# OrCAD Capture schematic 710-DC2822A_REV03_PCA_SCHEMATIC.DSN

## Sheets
1 PAGE1: company: ANALOG DEVICES; note: DEMO BOARD BILL OF MATERIALS; note: HIGH EFFICIENCY 65V/100mA SYNCHRONOUS BUCK
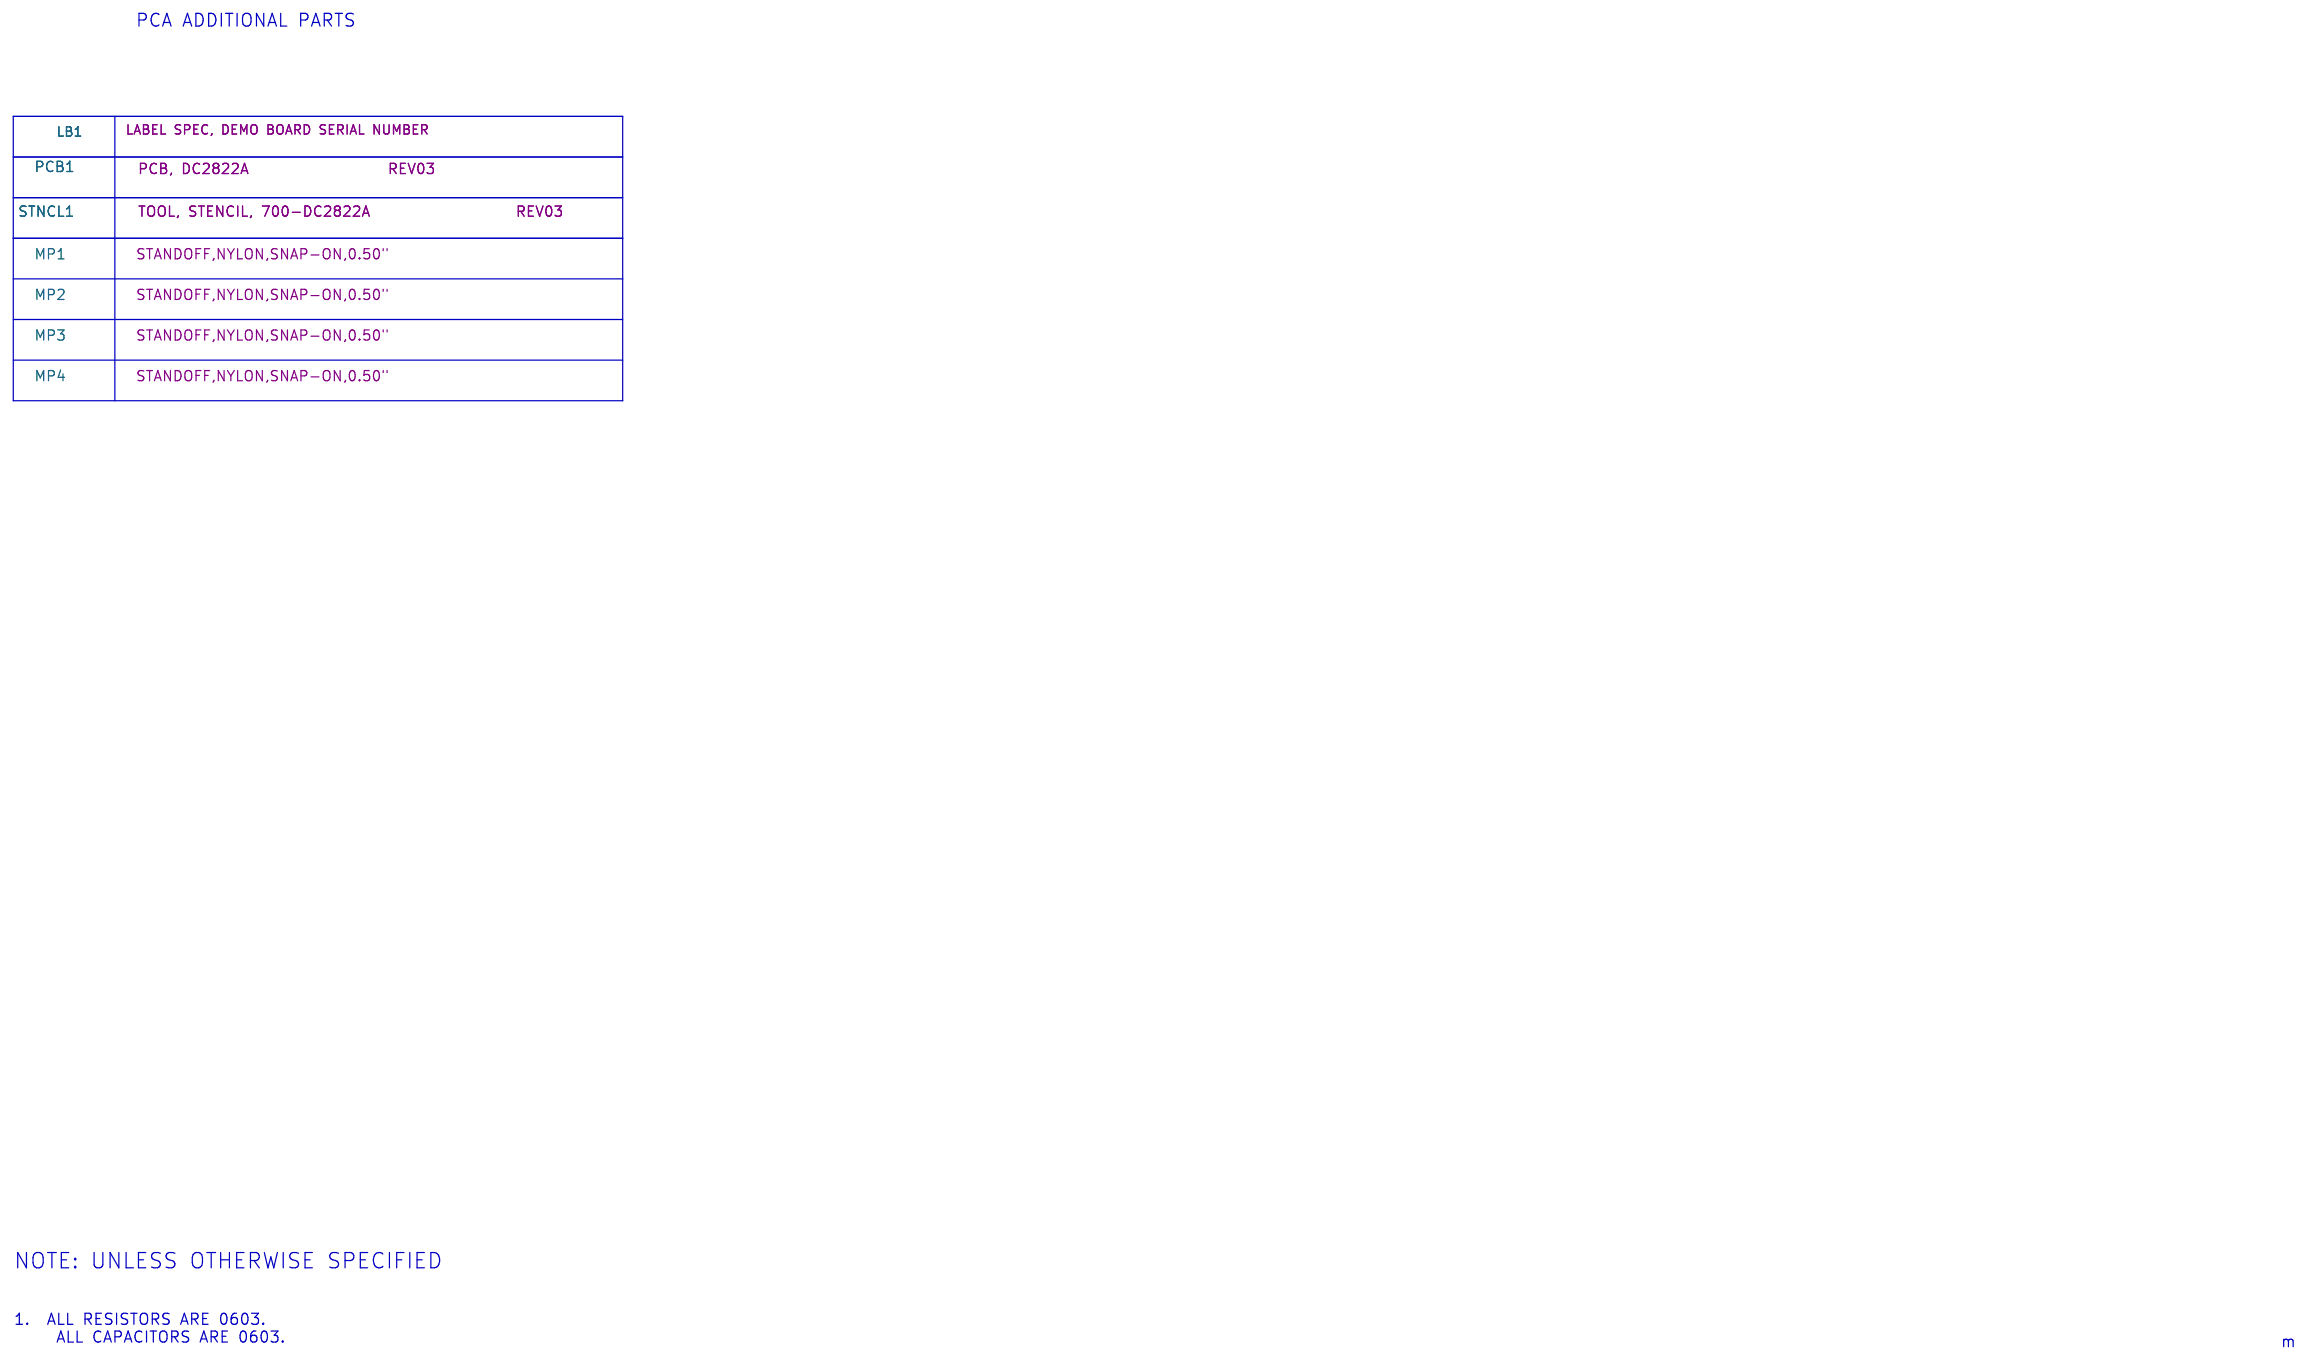
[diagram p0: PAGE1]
2 DC2822A: size Custom
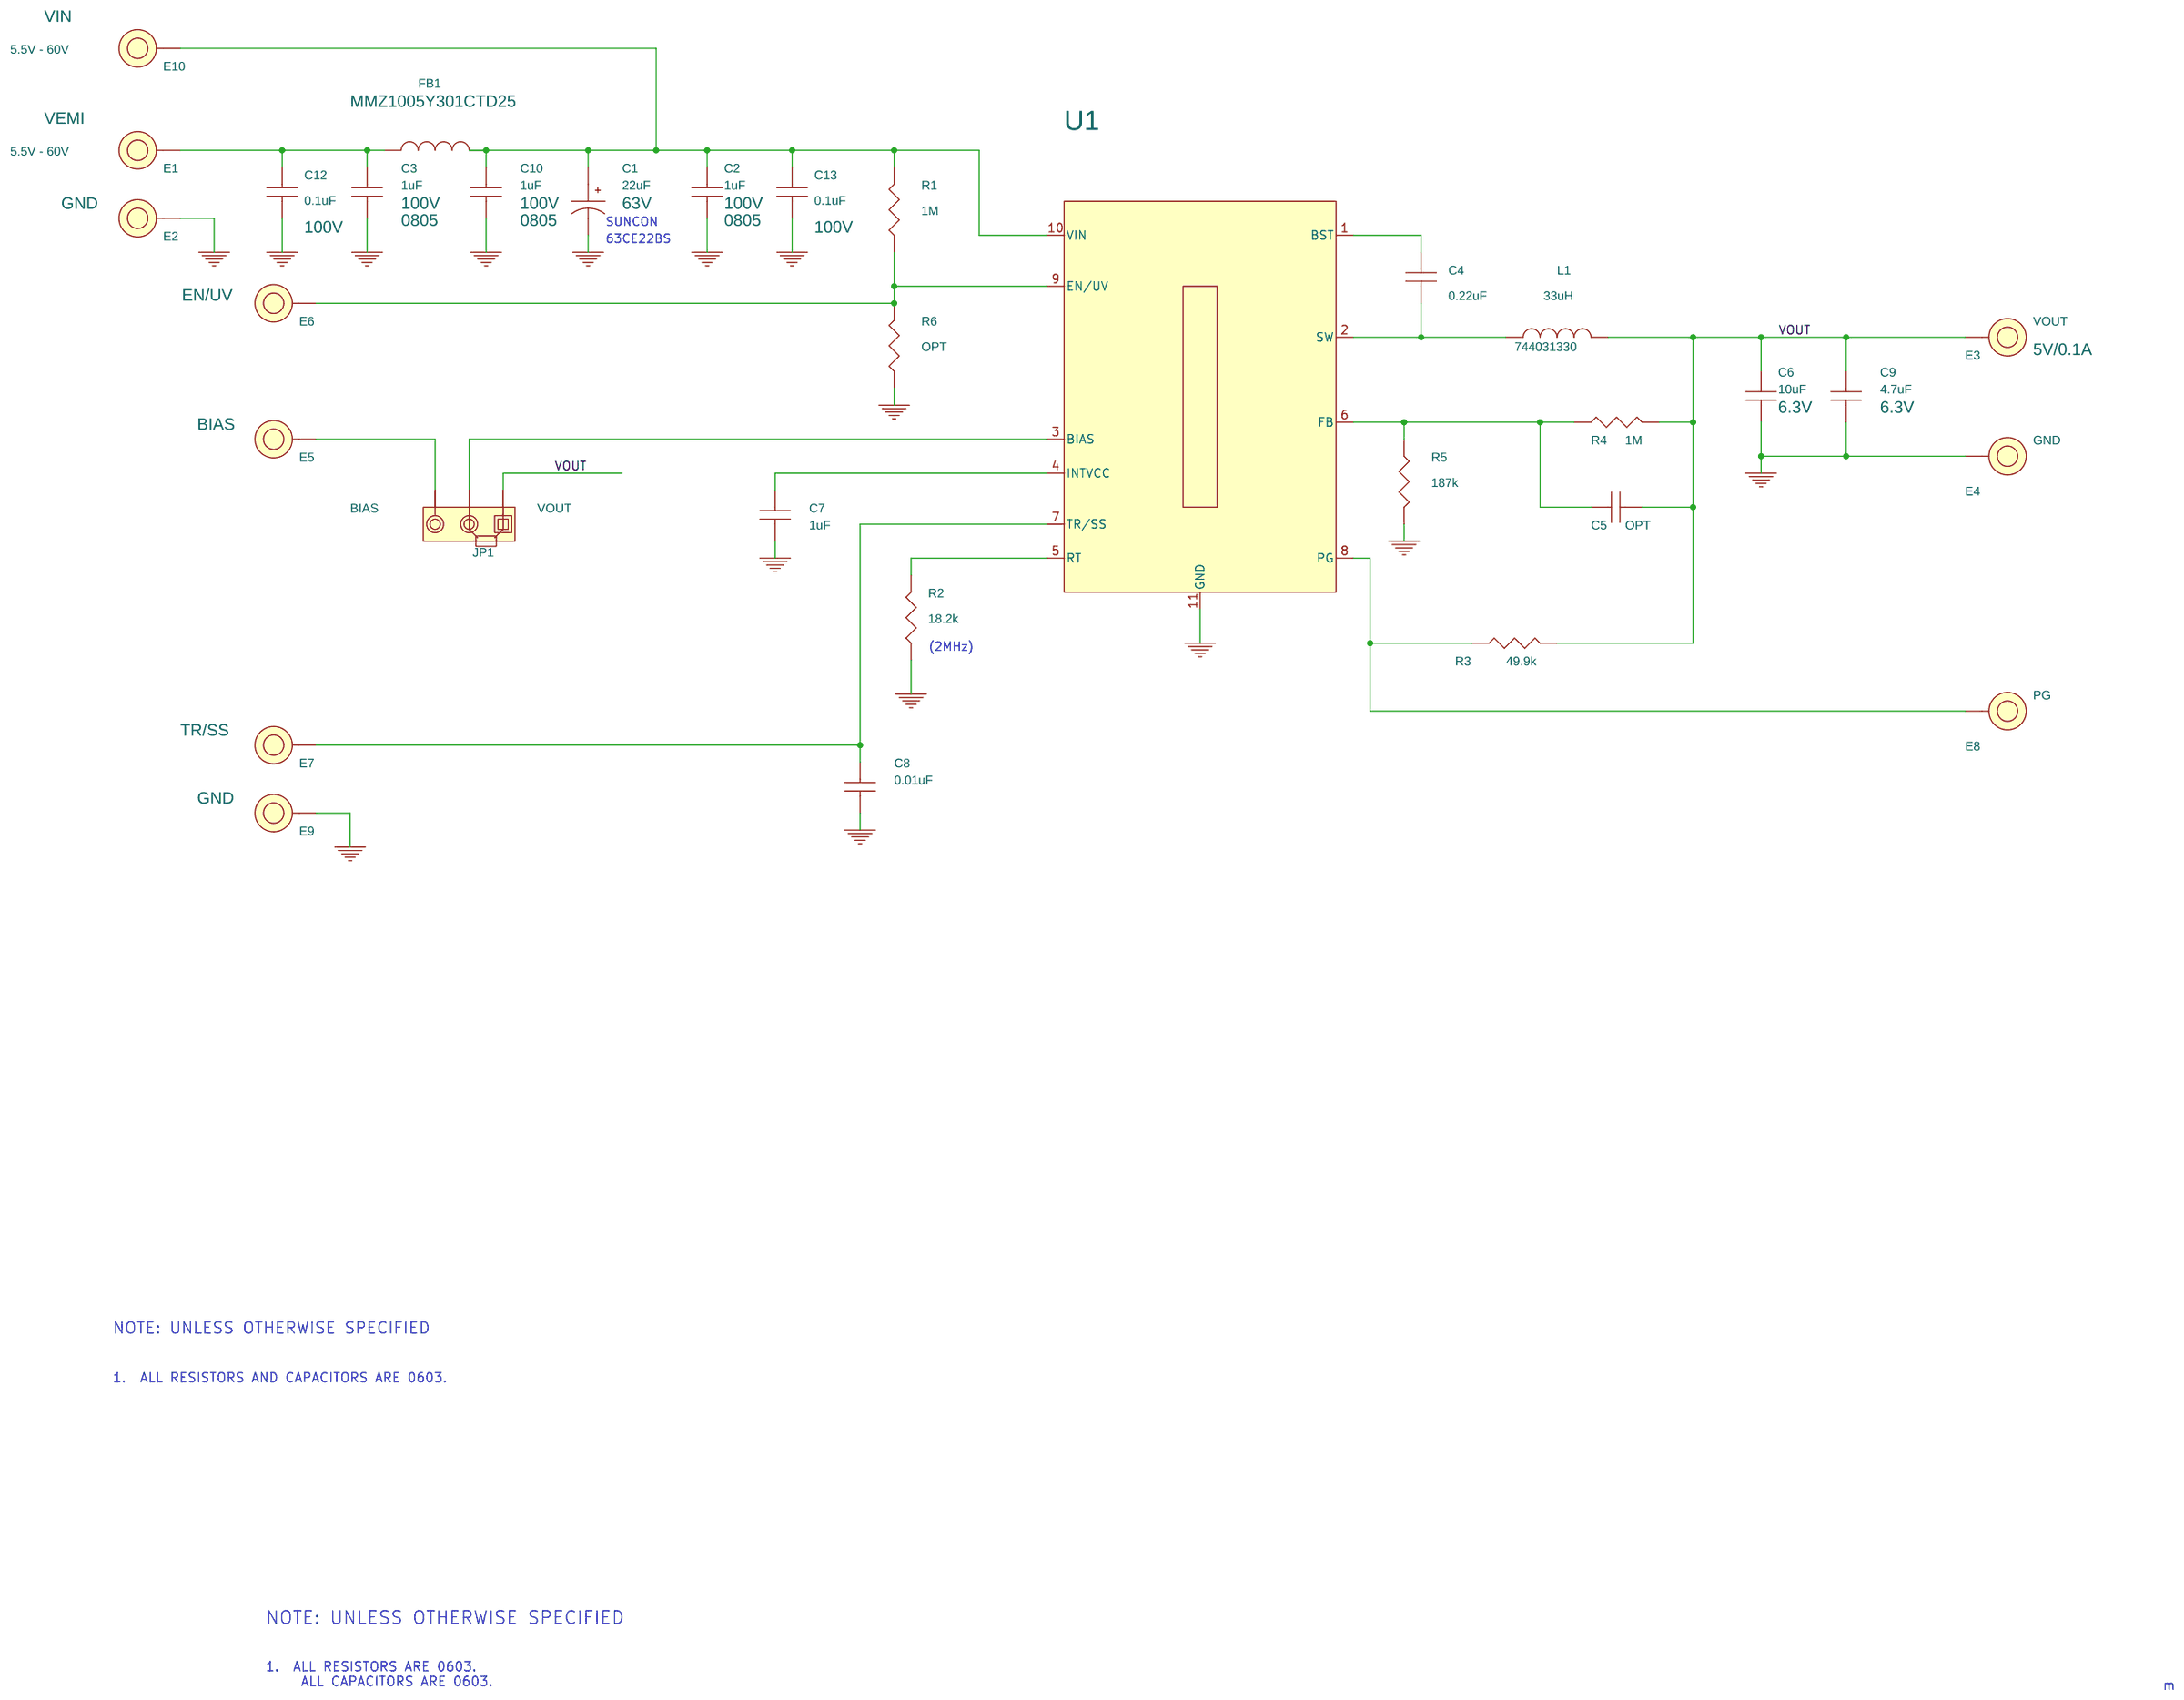
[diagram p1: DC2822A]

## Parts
sheet DC2822A
C1  22uF  [SUNCON_CE-BS_6.3X7.7]
C2  1uF  [CC0805N]
C3  1uF  [CC0805N]
C4  0.22uF  [CC0603N]
C5  OPT  [CC0603N]
C6  10uF  [CC0603N]
C7  1uF  [CC0603N]
C8  0.01uF  [CC0603N]
C9  4.7uF  [CC0603N]
C10  1uF  [CC0805N]
C12  0.1uF  [CC0603N]
C13  0.1uF  [CC0603N]
E1  TEST POINT  [MILLMAX2501]
E2  TEST POINT  [MILLMAX2501]
E3  TEST POINT  [MILLMAX2501]
E4  TEST POINT  [MILLMAX2501]
E5  TEST POINT  [MILLMAX2501]
E6  TEST POINT  [MILLMAX2501]
E7  TEST POINT  [MILLMAX2501]
E8  TEST POINT  [MILLMAX2501]
E9  TEST POINT  [MILLMAX2501]
E10  TEST POINT  [MILLMAX2501]
FB1  300 OHMS@100MHz  [IND0402N]
JP1  HDR  [HD1X3-079]
L1  33uH  [WURTH-744031330]
R1  1M  [CR0603N]
R2  18.2k  [CR0603N]
R3  49.9k  [CR0603N]
R4  1M  [CR0603N]
R5  187k  [CR0603N]
R6  OPT  [CR0603N]
U1  LT8618-DDB  [LTC-DDB-10-1722]
XJP1  SHUNT
sheet PAGE1
LB1  LABEL  [895-0154_REV01]
MP1  STANDOFF  [KEYSTONE_8829-8834]
MP2  STANDOFF  [KEYSTONE_8829-8834]
MP3  STANDOFF  [KEYSTONE_8829-8834]
MP4  STANDOFF  [KEYSTONE_8829-8834]
PCB1  PCB, DC2822A
STNCL1  TOOL, STENCIL, 700-DC2822A

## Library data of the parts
C1 = CAP_P: CAP.,22uF,ALUM. ELECT.,63V,20%,6.3x7.7mm,CE-BS; CLASS: DISCRETE; Dielectric Type: ALUM. ELECT.; Inventory Qty: 35902; Manufacturer: SUN ELECTRONIC INDUSTRIES CORP; Manufacturer PN: 63CE22BS; PART_NUMBER: 150-3334; Package Size: 6.3x7.7mm; Rated Voltage: 63V; Tolerance: 20%
C2 C10 = CAP: CAP.,1uF,X7S,100V,20%,0805; CLASS: DISCRETE; Dielectric Type: X7S; FPLIST: CC0805N,CC0805L,CC0805M; Inventory Qty: 8512; Manufacturer: MURATA; Manufacturer PN: GRJ21BC72A105ME11L; PART_NUMBER: 150-2447; Package Size: 0805; Rated Voltage: 100V; Tolerance: 20%
C3 = CAP: CAP.,1uF,X7S,100V,20%,0805; CLASS: DISCRETE; Dielectric Type: X7S; Inventory Qty: 8512; Manufacturer: MURATA; Manufacturer PN: GRJ21BC72A105ME11L; PART_NUMBER: 150-2447; Package Size: 0805; Rated Voltage: 100V; Tolerance: 20%
C4 = CAP: CAP.,0.22uF,X7R,16V,10%,0603; CLASS: DISCRETE; Dielectric Type: X7R; FPLIST: CC0603N,CC0603L,CC0603M; Inventory Qty: 18099; Manufacturer: AVX; Manufacturer PN: 0603YC224KAT2A; PART_NUMBER: 150-0181; Package Size: 0603; Rated Voltage: 16V; Tolerance: 10%
C5 = CAP: CAP., OPTION, 0603; CLASS: DISCRETE; FPLIST: CC0603N,CC0603L,CC0603M; PART_NUMBER: 150-3038; Package Size: 0603; Package Type: SMD
C6 = CAP: CAP.,10uF,X5R,6.3V,20%,0603; CLASS: DISCRETE; Dielectric Type: X5R; FPLIST: CC0603N,CC0603L,CC0603M; Inventory Qty: 63391; Manufacturer: MURATA; Manufacturer PN: GRM188R60J106ME47D; PART_NUMBER: 150-3401; Package Size: 0603; Package Type: SMD; Rated Voltage: 6.3V; Tolerance: 20%
C7 = CAP: CAP.,1uF,X7R,16V,10%,0603; CLASS: DISCRETE; Dielectric Type: X7R; Inventory Qty: 29469; Manufacturer: KEMET; Manufacturer PN: C0603C105K4RAC7867; PART_NUMBER: 150-0179; Package Size: 0603; Rated Voltage: 16V; Tolerance: 10%
C8 = CAP: CAP.,0.01uF,X7R,16V,10%,0603; CLASS: DISCRETE; Dielectric Type: X7R; FPLIST: CC0603N,CC0603L,CC0603M; Inventory Qty: 68392; Manufacturer: AVX; Manufacturer PN: 0603YC103KAT2A; PART_NUMBER: 150-0038; Package Size: 0603; Rated Voltage: 16V; Tolerance: 10%
C9 = CAP: CAP.,4.7uF,X5R,6.3V,10%,0603; CLASS: DISCRETE; Dielectric Type: X5R; FPLIST: CC0603N,CC0603L,CC0603M; Inventory Qty: 21980; Manufacturer: KEMET; Manufacturer PN: C0603C475K9PACTU; PART_NUMBER: 150-0129; Package Size: 0603; Rated Voltage: 6.3V; Tolerance: 10%
C12 C13 = CAP: CAP.,0.1uF,X7R,100V,10%,0603; CLASS: DISCRETE; Dielectric Type: X7R; FPLIST: CC0603N,CC0603L,CC0603M; Inventory Qty: 37568; Manufacturer: AVX; Manufacturer PN: 06031C104KAT2A; PART_NUMBER: 150-3294; Package Size: 0603; Rated Voltage: 100V; Tolerance: 10%
E1 = TESTPOINT_.219_MILL-MAX_2501_A: TEST POINT,TURRET,0.094" MTG. HOLE,PCB 0.062" THK; CLASS: IO; Inventory Qty: 387967; Manufacturer: MILL-MAX; Manufacturer PN: 2501-2-00-80-00-00-07-0; PART_FIELD_01: 5.5V - 60V; PART_FIELD_02: VEMI; PART_NUMBER: 260-0003
E2 E9 = TESTPOINT_.219_MILL-MAX_2501_A: TEST POINT,TURRET,0.094" MTG. HOLE,PCB 0.062" THK; CLASS: IO; Inventory Qty: 387967; Manufacturer: MILL-MAX; Manufacturer PN: 2501-2-00-80-00-00-07-0; PART_FIELD_02: GND; PART_NUMBER: 260-0003
E3 = TESTPOINT_.219_MILL-MAX_2501_A: TEST POINT,TURRET,0.094" MTG. HOLE,PCB 0.062" THK; CLASS: IO; Inventory Qty: 387967; Manufacturer: MILL-MAX; Manufacturer PN: 2501-2-00-80-00-00-07-0; PART_FIELD_01: VOUT; PART_FIELD_02: 5V/0.1A; PART_NUMBER: 260-0003
E4 = TESTPOINT_.219_MILL-MAX_2501_A: TEST POINT,TURRET,0.094" MTG. HOLE,PCB 0.062" THK; CLASS: IO; Inventory Qty: 387967; Manufacturer: MILL-MAX; Manufacturer PN: 2501-2-00-80-00-00-07-0; PART_FIELD_01: GND; PART_NUMBER: 260-0003
E5 = TESTPOINT_.219_MILL-MAX_2501_A: TEST POINT,TURRET,0.094" MTG. HOLE,PCB 0.062" THK; CLASS: IO; Inventory Qty: 387967; Manufacturer: MILL-MAX; Manufacturer PN: 2501-2-00-80-00-00-07-0; PART_FIELD_02: BIAS; PART_NUMBER: 260-0003
E6 = TESTPOINT_.219_MILL-MAX_2501_A: TEST POINT,TURRET,0.094" MTG. HOLE,PCB 0.062" THK; CLASS: IO; Inventory Qty: 387967; Manufacturer: MILL-MAX; Manufacturer PN: 2501-2-00-80-00-00-07-0; PART_FIELD_02: EN/UV; PART_NUMBER: 260-0003
E7 = TESTPOINT_.219_MILL-MAX_2501_A: TEST POINT,TURRET,0.094" MTG. HOLE,PCB 0.062" THK; CLASS: IO; Inventory Qty: 387967; Manufacturer: MILL-MAX; Manufacturer PN: 2501-2-00-80-00-00-07-0; PART_FIELD_02: TR/SS; PART_NUMBER: 260-0003
E8 = TESTPOINT_.219_MILL-MAX_2501_A: TEST POINT,TURRET,0.094" MTG. HOLE,PCB 0.062" THK; CLASS: IO; Inventory Qty: 387967; Manufacturer: MILL-MAX; Manufacturer PN: 2501-2-00-80-00-00-07-0; PART_FIELD_01: PG; PART_NUMBER: 260-0003
E10 = TESTPOINT_.219_MILL-MAX_2501_A: TEST POINT,TURRET,0.094" MTG. HOLE,PCB 0.062" THK; CLASS: IO; Inventory Qty: 387967; Manufacturer: MILL-MAX; Manufacturer PN: 2501-2-00-80-00-00-07-0; PART_FIELD_01: 5.5V - 60V; PART_FIELD_02: VIN; PART_NUMBER: 260-0003
FB1 = IND: IND.,300 OHMS@100MHz,FERRITE BEAD,25%,250mA,380mOHMS,0402,1LN,AEC-Q200; CLASS: DISCRETE; FPLIST: IND0402N,IND0402L,IND0402M; Inventory Qty: 0; Manufacturer: TDK; Manufacturer PN: MMZ1005Y301CTD25; PART_NUMBER: 200-0804; Package Size: 0402; Tolerance: 25%
JP1 = 1X3_A: CONN.,HDR,MALE,1x3,2mm,VERT,ST,THT,NO SUBS. ALLOWED; 10th Part Field: BIAS; 9th Part Field: VOUT; CLASS: IO; Inventory Qty: 26994; Manufacturer: Wurth Elektronik; Manufacturer PN: 62000311121; PART_NUMBER: 250-0639
L1 = IND: IND.,33uH,PWR, SHIELDED,30%,0.42A,660mOhms,3816; CLASS: DISCRETE; Inventory Qty: 0; Manufacturer: WURTH ELEKTRONIK; Manufacturer PN: 744031330; PART_NUMBER: 200-0576; Package Size: 3816; Tolerance: 30%
R1 R4 = RES: RES.,1M OHM,1%,1/10W,0603,AEC-Q200; CLASS: DISCRETE; FPLIST: CR0603N,CR0603L,CR0603M; Inventory Qty: 163558; Manufacturer: VISHAY; Manufacturer PN: CRCW06031M00FKEA; PART_NUMBER: 100-0335; Package Size: 0603; Rated Power: 1/10W; Temperature Coefficient: 100ppm; Tolerance: 1%
R2 = RES: RES.,18.2k OHMS,1%,1/10W,0603,AEC-Q200; CLASS: DISCRETE; FPLIST: CR0603N,CR0603L,CR0603M; Inventory Qty: 98884; Manufacturer: PANASONIC; Manufacturer PN: ERJ3EKF1822; PART_NUMBER: 100-2916; Package Size: 0603; Rated Power: 1/10W; Temperature Coefficient: +/-100; Tolerance: 1%
R3 = RES: RES.,49.9k OHMS,1%,1/10W,0603; CLASS: DISCRETE; Inventory Qty: 84377; Manufacturer: NIC; Manufacturer PN: NRC06F4992TRF; PART_NUMBER: 100-0303; Package Size: 0603; Rated Power: 1/10W; Temperature Coefficient: 100ppm/C; Tolerance: 1%
R5 = RES: RES.,187k OHMS,1%,1/10W,0603,AEC-Q200; CLASS: DISCRETE; FPLIST: CR0603N,CR0603L,CR0603M; Inventory Qty: 18695; Manufacturer: PANASONIC; Manufacturer PN: ERJ3EKF1873V; PART_NUMBER: 100-2915; Package Size: 0603; Rated Power: 1/10W; Temperature Coefficient: +/-100; Tolerance: 1%
R6 = RES: RES., OPTION, 0603; CLASS: DISCRETE; FPLIST: CR0603N,CR0603L,CR0603M; PART_NUMBER: 100-2374; Package Size: 0603
U1 = LT8618-DDB: IC,60V 100mA BUCK REGULATOR,DFN-10; CLASS: IC; Inventory Qty: 0; Manufacturer: LINEAR TECH.; Manufacturer PN: LT8618EDDB#PBF; PART_NUMBER: LT8618EDDB#PBF; Package Type: DFN-10
XJP1 = SHUNT_2MM: CONN.,SHUNT,FEMALE,2 POS,2mm; CLASS: IO; Inventory Qty: 71650; Manufacturer: Wurth Elektronik; Manufacturer PN: 60800213421; PART_NUMBER: 250-0485
LB1 = BLANK_LABEL: LABEL SPEC, DEMO BOARD SERIAL NUMBER; Inventory Qty: 0; Manufacturer: BRADY; Manufacturer PN: THT-96-717-10; PART_NUMBER: 895-0154
MP1-MP4 = BLANK_MECHANICAL_PART: STANDOFF,NYLON,SNAP-ON,0.50"; CLASS: DISCRETE; Inventory Qty: 9693; Manufacturer: WURTH ELEKTRONIK; Manufacturer PN: 702935000; PART_NUMBER: 763-0020
PCB1 = BLANK_PCB_PART: BOM Notes: REV03; CLASS: DISCRETE; Inventory Qty: 0; Manufacturer: EAGLE TECH. INC.; Manufacturer PN: 600-DC2822A; PART_NUMBER: 600-DC2822A
STNCL1 = BLANK_STENCIL_PART: BOM Notes: REV03; CLASS: DISCRETE; Inventory Qty: 0; Manufacturer: LINEAR TECH.; Manufacturer PN: 830-DC2822A; PART_NUMBER: 830-DC2822A

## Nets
Dgnd: C1.2 C2.2 C3.2 C6.2 C7.2 C8.2 C9.2 C10.2 C12.2 C13.2 E2.1 E4.1 E9.1 R2.1 R5.2 R6.1 U1.11(GND)
VOUT: C5.2 C6.1 C9.1 E3.1 JP1.1 L1.2 R3.2 R4.2
N16999446: C1.1 C2.1 C10.1 C13.1 E10.1 FB1.2 R1.2 U1.10(VIN)
N16999468: C3.1 C12.1 E1.1 FB1.1
N16999621: C4.1 U1.1(BST)
N16999658: E6.1 R1.1 R6.2 U1.9(EN/UV)
N16999666: C4.2 L1.1 U1.2(SW)
N16999756: C5.1 R4.1 R5.1 U1.6(FB)
N16999774: E5.1 JP1.3
N16999778: JP1.2 U1.3(BIAS)
N16999808: C7.1 U1.4(INTVCC)
N16999846: C8.1 E7.1 U1.7(TR/SS)
N16999856: R2.2 U1.5(RT)
N16999860: E8.1 R3.1 U1.8(PG)

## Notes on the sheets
sheet 1
- PCA ADDITIONAL PARTS
- NOTE: UNLESS OTHERWISE SPECIFIED
- 1.  ALL RESISTORS ARE 0603.
       ALL CAPACITORS ARE 0603.
- m
sheet 2
- SUNCON
- 63CE22BS
- (2MHz)
- NOTE: UNLESS OTHERWISE SPECIFIED
- 1.  ALL RESISTORS AND CAPACITORS ARE 0603.
- NOTE: UNLESS OTHERWISE SPECIFIED
- 1.  ALL RESISTORS ARE 0603.
       ALL CAPACITORS ARE 0603.
- m
